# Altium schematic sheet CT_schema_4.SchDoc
size 283 x 147 mm
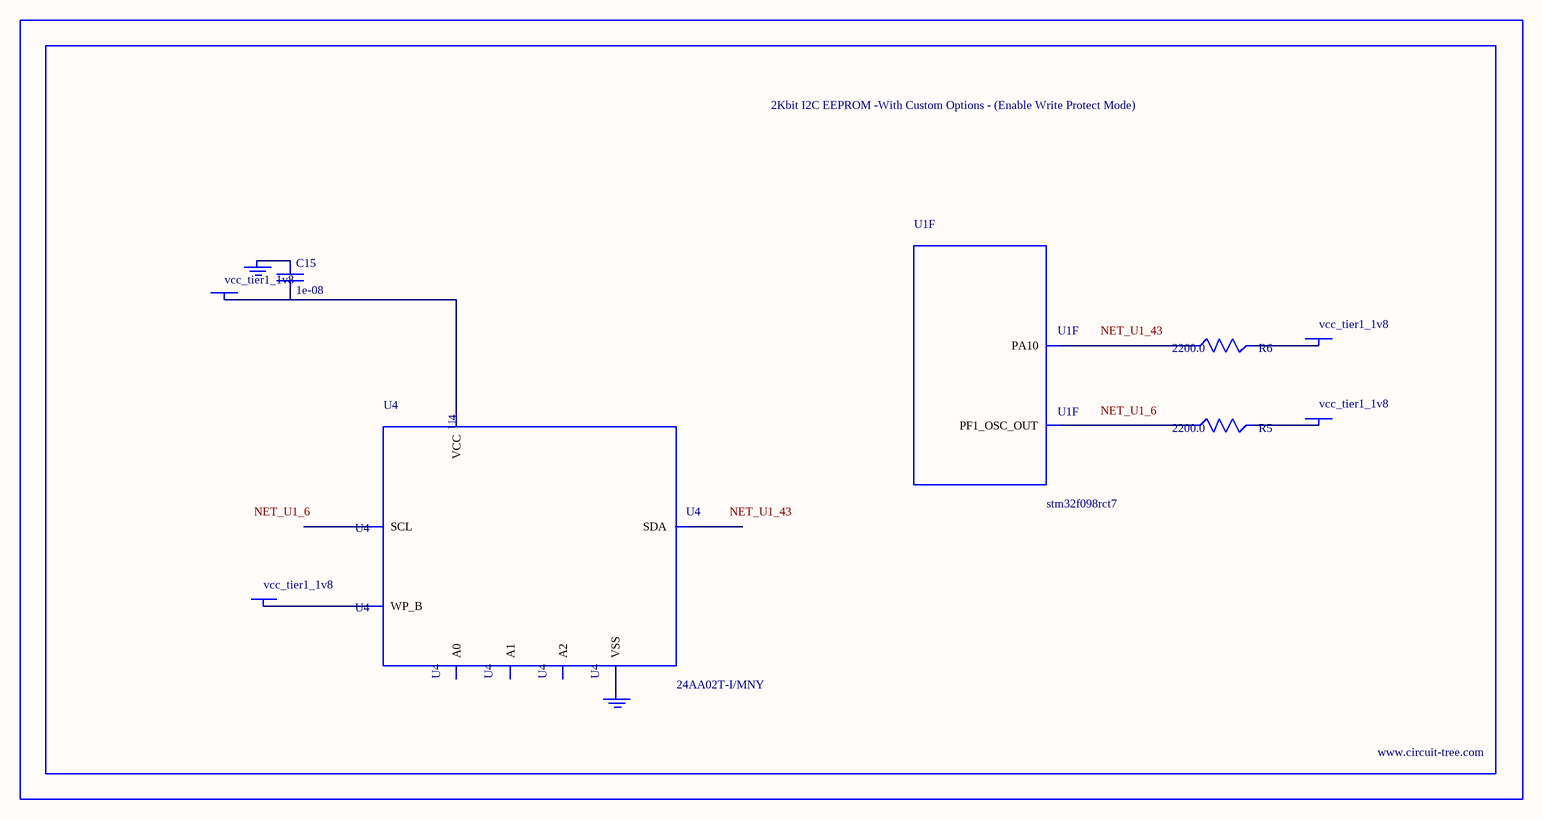
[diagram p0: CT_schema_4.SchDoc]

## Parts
BORDER3  (no value)
C15  1e-08  [C0402]
GND_INSTANCE_3_0  (no value)
GND_INSTANCE_3_1  (no value)
POWER_INSTANCE_3_0  vcc_tier1_1v8
POWER_INSTANCE_3_1  vcc_tier1_1v8
POWER_INSTANCE_3_2  vcc_tier1_1v8
POWER_INSTANCE_3_3  vcc_tier1_1v8
R5  2200.0  [R0603]
R6  2200.0  [R0603]
U1  stm32f098rct7  [LQFP64]  (part F of 7)
U4  24AA02T-I/MNY  [TDFN-8/6MM]

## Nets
NetC15_1: C15.1 GND_INSTANCE_3_0.0(GND)
NetC15_2: C15.2 POWER_INSTANCE_3_1.0(PWR) U4.8(VCC)
NetGND_INSTANCE_3_1_0: GND_INSTANCE_3_1.0(GND) U4.4(VSS)
NetPOWER_INSTANCE_3_0_0: POWER_INSTANCE_3_0.0(PWR) U4.7(WP_B)
NetPOWER_INSTANCE_3_2_0: POWER_INSTANCE_3_2.0(PWR) R5.2
NetPOWER_INSTANCE_3_3_0: POWER_INSTANCE_3_3.0(PWR) R6.2
NetR5_1: R5.1 U1.6(PF1_OSC_OUT)
NetR6_1: R6.1 U1.43(PA10)

Not connected (* = marked no-connect by the designer): U4 1(A0) 2(A1) 3(A2) 5(SDA) 6(SCL)

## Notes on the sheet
- Labels drawn without touching a wire or pin: NET_U1_6, NET_U1_43

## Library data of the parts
BORDER3 = BORDER_PAGE3
C15 = C0402C103K3RAC
GND_INSTANCE_3_0 GND_INSTANCE_3_1 = GND
POWER_INSTANCE_3_0-POWER_INSTANCE_3_3 = PWR
R5 R6 = RC0603JR-072K2L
